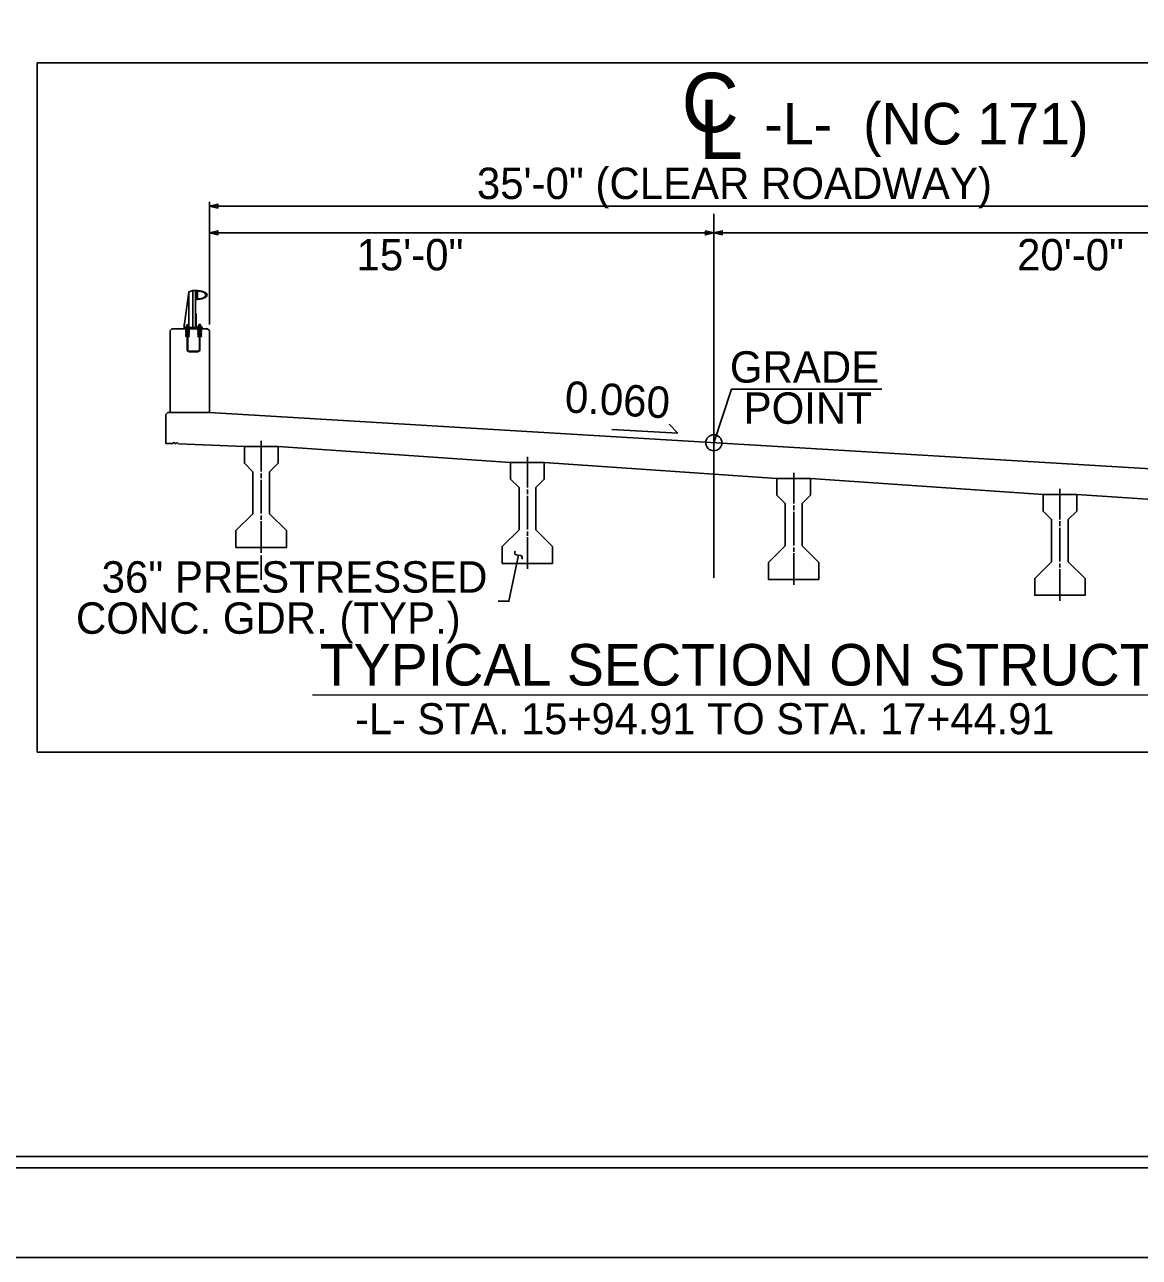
# Model space of a CAD drawing. Extents: x 2532463 to 2534146, y 189689 to 190784.
# Drawn here: x 2532655.1 to 2532903.7, y 189689.2 to 189964.1 of the extents above; entities that cross this region are included whole.
import ezdxf

# ---------------------------------------------------------------- set-up
doc = ezdxf.new("R2010")
doc.units = 0
for name, color, linetype in [('Default', 7, 'Continuous'), ('Old_Level_1', 7, 'Continuous'), ('Old_Level_18', 7, 'Continuous'), ('Old_Level_2', 7, 'Continuous'), ('Old_Level_3', 7, 'Continuous'), ('Old_Level_50', 7, 'Continuous'), ('Old_Level_51', 7, 'Continuous')]:
    doc.layers.add(name, color=color, linetype=linetype)

msp = doc.modelspace()

# ---------------------------------------------------------------- linework, layer by layer
at = {"layer": 'Default'}
for p, q in [((2532696.33, 189897.82), (2532696.33, 189924.57)), ((2532696.33, 189923.63), (2532958.83, 189923.63)), ((2532808.83, 189840.77), (2532808.83, 189921.89)), ((2532696.33, 189897.82), (2532696.33, 189918.63)), ((2532696.33, 189897.26), (2532696.33, 189918.63)), ((2532808.83, 189915.84), (2532808.83, 189918.63)), ((2532696.33, 189917.69), (2532808.83, 189917.69)), ((2532808.83, 189917.69), (2532958.83, 189917.69)), ((2532691.74, 189904.56), (2532690.71, 189896.89)), ((2532691.74, 189904.27), (2532691.7, 189904.27)), ((2532691.74, 189904.56), (2532692.63, 189904.85)), ((2532691.74, 189896.6), (2532691.74, 189904.56)), ((2532693.21, 189904.85), (2532692.63, 189904.85)), ((2532692.63, 189896.6), (2532692.63, 189904.85)), ((2532693.21, 189896.6), (2532693.21, 189904.85)), ((2532693.71, 189904.61), (2532693.71, 189903.81)), ((2532693.71, 189903.01), (2532693.71, 189903.81)), ((2532687.59, 189895.92), (2532687.98, 189896.31)), ((2532687.59, 189895.92), (2532687.59, 189877.61)), ((2532695.95, 189896.31), (2532687.98, 189896.31)), ((2532690.71, 189896.6), (2532690.71, 189896.89)), ((2532690.74, 189897.06), (2532690.74, 189897.32)), ((2532691.83, 189896.02), (2532691.05, 189896.02)), ((2532691.83, 189895.94), (2532691.05, 189895.94)), ((2532691.37, 189895.85), (2532691.22, 189895.85)), ((2532691.27, 189895.95), (2532691.27, 189896.6)), ((2532691.62, 189897.19), (2532691.28, 189897.19)), ((2532691.28, 189897.19), (2532691.28, 189896.92)), ((2532691.5, 189895.85), (2532691.37, 189895.85)), ((2532691.37, 189895.85), (2532691.37, 189891.7)), ((2532691.66, 189895.85), (2532691.5, 189895.85)), ((2532691.5, 189895.85), (2532691.5, 189891.7)), ((2532691.61, 189895.95), (2532691.61, 189896.6)), ((2532691.62, 189896.92), (2532691.62, 189897.19)), ((2532694.55, 189896.02), (2532693.77, 189896.02)), ((2532694.55, 189895.94), (2532693.77, 189895.94)), ((2532694.1, 189895.85), (2532693.94, 189895.85)), ((2532693.99, 189896.02), (2532693.99, 189896.67)), ((2532694.34, 189897.27), (2532694.01, 189897.27)), ((2532694.01, 189897.27), (2532694.01, 189896.99)), ((2532694.23, 189895.85), (2532694.1, 189895.85)), ((2532694.1, 189895.85), (2532694.1, 189891.7)), ((2532694.38, 189895.85), (2532694.23, 189895.85)), ((2532694.23, 189895.85), (2532694.23, 189891.7)), ((2532694.34, 189896.99), (2532694.34, 189897.27)), ((2532694.36, 189896.02), (2532694.36, 189896.67)), ((2532695.95, 189896.31), (2532696.33, 189895.92)), ((2532696.33, 189895.92), (2532696.33, 189877.61)), ((2532691.37, 189895.68), (2532691.05, 189895.68)), ((2532691.37, 189895.59), (2532691.05, 189895.59)), ((2532691.37, 189895.33), (2532691.05, 189895.33)), ((2532691.37, 189895.24), (2532691.05, 189895.24)), ((2532691.37, 189894.98), (2532691.05, 189894.98)), ((2532691.37, 189894.9), (2532691.05, 189894.9)), ((2532691.37, 189894.63), (2532691.05, 189894.63)), ((2532691.37, 189894.55), (2532691.05, 189894.55)), ((2532691.37, 189895.76), (2532691.22, 189895.76)), ((2532691.37, 189895.5), (2532691.22, 189895.5)), ((2532691.37, 189895.41), (2532691.22, 189895.41)), ((2532691.37, 189895.15), (2532691.22, 189895.15)), ((2532691.37, 189895.07), (2532691.22, 189895.07)), ((2532691.37, 189894.81), (2532691.22, 189894.81)), ((2532691.37, 189894.72), (2532691.22, 189894.72)), ((2532691.66, 189895.76), (2532691.5, 189895.76)), ((2532691.83, 189895.68), (2532691.5, 189895.68)), ((2532691.83, 189895.59), (2532691.5, 189895.59)), ((2532691.66, 189895.5), (2532691.5, 189895.5)), ((2532691.66, 189895.41), (2532691.5, 189895.41)), ((2532691.83, 189895.33), (2532691.5, 189895.33)), ((2532691.83, 189895.24), (2532691.5, 189895.24)), ((2532691.66, 189895.15), (2532691.5, 189895.15)), ((2532691.66, 189895.07), (2532691.5, 189895.07)), ((2532691.83, 189894.98), (2532691.5, 189894.98)), ((2532691.83, 189894.9), (2532691.5, 189894.9)), ((2532691.66, 189894.81), (2532691.5, 189894.81)), ((2532691.66, 189894.72), (2532691.5, 189894.72)), ((2532691.83, 189894.63), (2532691.5, 189894.63)), ((2532691.83, 189894.55), (2532691.5, 189894.55)), ((2532694.1, 189895.68), (2532693.77, 189895.68)), ((2532694.1, 189895.59), (2532693.77, 189895.59)), ((2532694.1, 189895.33), (2532693.77, 189895.33)), ((2532694.1, 189895.24), (2532693.77, 189895.24)), ((2532694.1, 189894.98), (2532693.77, 189894.98)), ((2532694.1, 189894.9), (2532693.77, 189894.9)), ((2532694.1, 189894.63), (2532693.77, 189894.63)), ((2532694.1, 189894.55), (2532693.77, 189894.55)), ((2532694.1, 189895.76), (2532693.94, 189895.76)), ((2532694.1, 189895.5), (2532693.94, 189895.5)), ((2532694.1, 189895.41), (2532693.94, 189895.41)), ((2532694.1, 189895.15), (2532693.94, 189895.15)), ((2532694.1, 189895.07), (2532693.94, 189895.07)), ((2532694.1, 189894.81), (2532693.94, 189894.81)), ((2532694.1, 189894.72), (2532693.94, 189894.72)), ((2532694.38, 189895.76), (2532694.23, 189895.76)), ((2532694.55, 189895.68), (2532694.23, 189895.68)), ((2532694.55, 189895.59), (2532694.23, 189895.59)), ((2532694.38, 189895.5), (2532694.23, 189895.5)), ((2532694.38, 189895.41), (2532694.23, 189895.41)), ((2532694.55, 189895.33), (2532694.23, 189895.33)), ((2532694.55, 189895.24), (2532694.23, 189895.24)), ((2532694.38, 189895.15), (2532694.23, 189895.15)), ((2532694.38, 189895.07), (2532694.23, 189895.07)), ((2532694.55, 189894.98), (2532694.23, 189894.98)), ((2532694.55, 189894.9), (2532694.23, 189894.9)), ((2532694.38, 189894.81), (2532694.23, 189894.81)), ((2532694.38, 189894.72), (2532694.23, 189894.72)), ((2532694.55, 189894.63), (2532694.23, 189894.63)), ((2532694.55, 189894.55), (2532694.23, 189894.55)), ((2532693.68, 189891.29), (2532691.92, 189891.29)), ((2532693.68, 189891.16), (2532691.92, 189891.16)), ((2532808.83, 189870.86), (2532812.79, 189882.8)), ((2532812.79, 189882.8), (2532846.28, 189882.8)), ((2532686.64, 189877.19), (2532687.04, 189877.61)), ((2532687.67, 189877.61), (2532687.04, 189877.61)), ((2532696.33, 189877.61), (2532687.67, 189877.61)), ((2532800.78, 189872.97), (2532786.07, 189873.85)), ((2532800.78, 189872.97), (2532798.85, 189875.01)), ((2532707.89, 189871.29), (2532707.89, 189864.42)), ((2532767.27, 189867.72), (2532767.27, 189860.86)), ((2532707.89, 189864.03), (2532707.89, 189862.94)), ((2532826.64, 189864.16), (2532826.64, 189857.3)), ((2532707.89, 189862.6), (2532707.89, 189855.06)), ((2532767.27, 189860.47), (2532767.27, 189859.37)), ((2532886.02, 189860.6), (2532886.02, 189853.74)), ((2532767.27, 189859.04), (2532767.27, 189851.49)), ((2532707.89, 189854.63), (2532707.89, 189853.69)), ((2532826.64, 189856.9), (2532826.64, 189855.81)), ((2532826.64, 189855.48), (2532826.64, 189847.93)), ((2532707.89, 189853.39), (2532707.89, 189846.28)), ((2532886.02, 189853.34), (2532886.02, 189852.25)), ((2532886.02, 189851.92), (2532886.02, 189844.37)), ((2532767.27, 189851.07), (2532767.27, 189850.13)), ((2532767.27, 189849.83), (2532767.27, 189842.71)), ((2532764.45, 189846.43), (2532764.52, 189846.69)), ((2532826.64, 189847.51), (2532826.64, 189846.57)), ((2532707.89, 189845.71), (2532707.89, 189840.28)), ((2532765.63, 189845.75), (2532764.81, 189845.86)), ((2532766, 189844.91), (2532766.06, 189845.11)), ((2532826.64, 189846.26), (2532826.64, 189839.15)), ((2532886.02, 189843.94), (2532886.02, 189843.01)), ((2532886.02, 189842.7), (2532886.02, 189835.59))]:
    msp.add_line(p, q, dxfattribs=at)
for points in [[(2532698.2, 189923.16), (2532696.33, 189923.63), (2532698.2, 189924.1)], [(2532698.2, 189917.22), (2532696.33, 189917.69), (2532698.2, 189918.15)], [(2532806.95, 189918.15), (2532808.83, 189917.69), (2532806.95, 189917.22)], [(2532810.7, 189917.22), (2532808.83, 189917.69), (2532810.7, 189918.15)]]:
    msp.add_lwpolyline(points, close=True, dxfattribs=at)
for points in [[(2532693.21, 189902.79), (2532693.21, 189903.17), (2532693.37, 189903.17), (2532693.37, 189903.1), (2532693.36, 189903.1), (2532693.36, 189902.94), (2532693.61, 189902.94), (2532693.64, 189903.19), (2532693.64, 189903.81), (2532693.64, 189904.42), (2532693.61, 189904.67), (2532693.36, 189904.67), (2532693.36, 189904.51), (2532693.37, 189904.51), (2532693.37, 189904.44), (2532693.21, 189904.44), (2532693.21, 189904.83)], [(2532694.72, 189896.31), (2532694.72, 189896.67), (2532693.36, 189896.67), (2532693.36, 189899.69), (2532693.21, 189899.69), (2532693.21, 189896.6), (2532690.78, 189896.6), (2532690.78, 189896.82), (2532690.71, 189896.82), (2532690.71, 189896.31), (2532691.88, 189896.31), (2532691.88, 189896.51), (2532693.07, 189896.51), (2532693.07, 189896.31), (2532694.72, 189896.31)], [(2532691.05, 189896.02), (2532691.05, 189895.94), (2532691.22, 189895.85), (2532691.22, 189895.76), (2532691.05, 189895.68), (2532691.05, 189895.59), (2532691.22, 189895.5), (2532691.22, 189895.41), (2532691.05, 189895.33), (2532691.05, 189895.24), (2532691.22, 189895.15), (2532691.22, 189895.07), (2532691.05, 189894.98), (2532691.05, 189894.9), (2532691.22, 189894.81), (2532691.22, 189894.72), (2532691.05, 189894.63), (2532691.05, 189894.55)], [(2532691.78, 189896.6), (2532691.78, 189896.66), (2532691.45, 189896.66), (2532691.11, 189896.66), (2532691.11, 189896.6)], [(2532691.7, 189896.66), (2532691.7, 189896.88), (2532691.65, 189896.92), (2532691.24, 189896.92), (2532691.2, 189896.88), (2532691.2, 189896.66), (2532691.7, 189896.66), (2532691.53, 189896.66), (2532691.53, 189896.88), (2532691.57, 189896.92), (2532691.53, 189896.88), (2532691.49, 189896.92), (2532691.41, 189896.92), (2532691.36, 189896.88), (2532691.36, 189896.66), (2532691.36, 189896.88), (2532691.32, 189896.92)], [(2532691.83, 189896.02), (2532691.83, 189895.94), (2532691.66, 189895.85), (2532691.66, 189895.76), (2532691.83, 189895.68), (2532691.83, 189895.59), (2532691.66, 189895.5), (2532691.66, 189895.41), (2532691.83, 189895.33), (2532691.83, 189895.24), (2532691.66, 189895.15), (2532691.66, 189895.07), (2532691.83, 189894.98), (2532691.83, 189894.9), (2532691.66, 189894.81), (2532691.66, 189894.72), (2532691.83, 189894.63), (2532691.83, 189894.55)], [(2532693.77, 189896.02), (2532693.77, 189895.94), (2532693.94, 189895.85), (2532693.94, 189895.76), (2532693.77, 189895.68), (2532693.77, 189895.59), (2532693.94, 189895.5), (2532693.94, 189895.41), (2532693.77, 189895.33), (2532693.77, 189895.24), (2532693.94, 189895.15), (2532693.94, 189895.07), (2532693.77, 189894.98), (2532693.77, 189894.9), (2532693.94, 189894.81), (2532693.94, 189894.72), (2532693.77, 189894.63), (2532693.77, 189894.55)], [(2532694.52, 189896.67), (2532694.52, 189896.74), (2532694.18, 189896.74), (2532693.84, 189896.74), (2532693.84, 189896.67)], [(2532694.42, 189896.74), (2532694.42, 189896.95), (2532694.38, 189896.99), (2532693.97, 189896.99), (2532693.92, 189896.95), (2532693.92, 189896.74), (2532694.42, 189896.74), (2532694.25, 189896.74), (2532694.25, 189896.95), (2532694.3, 189896.99), (2532694.25, 189896.95), (2532694.22, 189896.99), (2532694.13, 189896.99), (2532694.09, 189896.95), (2532694.09, 189896.74), (2532694.09, 189896.95), (2532694.05, 189896.99)], [(2532694.55, 189896.02), (2532694.55, 189895.94), (2532694.38, 189895.85), (2532694.38, 189895.76), (2532694.55, 189895.68), (2532694.55, 189895.59), (2532694.38, 189895.5), (2532694.38, 189895.41), (2532694.55, 189895.33), (2532694.55, 189895.24), (2532694.38, 189895.15), (2532694.38, 189895.07), (2532694.55, 189894.98), (2532694.55, 189894.9), (2532694.38, 189894.81), (2532694.38, 189894.72), (2532694.55, 189894.63), (2532694.55, 189894.55)], [(2532707.89, 189870.04), (2532711.64, 189870.04), (2532711.64, 189866.29), (2532709.77, 189864.41), (2532709.77, 189855.03), (2532713.52, 189851.28), (2532713.52, 189847.53), (2532707.89, 189847.53), (2532702.26, 189847.53), (2532702.26, 189851.28), (2532706.02, 189855.03), (2532706.02, 189864.41), (2532704.14, 189866.29), (2532704.14, 189870.04), (2532707.89, 189870.04)], [(2532767.27, 189866.47), (2532771.02, 189866.47), (2532771.02, 189862.72), (2532769.14, 189860.85), (2532769.14, 189851.47), (2532772.89, 189847.72), (2532772.89, 189843.96), (2532767.27, 189843.96), (2532761.64, 189843.96), (2532761.64, 189847.72), (2532765.39, 189851.47), (2532765.39, 189860.85), (2532763.52, 189862.72), (2532763.52, 189866.47), (2532767.27, 189866.47)], [(2532826.64, 189862.91), (2532830.39, 189862.91), (2532830.39, 189859.16), (2532828.52, 189857.28), (2532828.52, 189847.91), (2532832.27, 189844.15), (2532832.27, 189840.4), (2532826.64, 189840.4), (2532821.01, 189840.4), (2532821.01, 189844.15), (2532824.77, 189847.91), (2532824.77, 189857.28), (2532822.89, 189859.16), (2532822.89, 189862.91), (2532826.64, 189862.91)], [(2532886.02, 189859.35), (2532889.77, 189859.35), (2532889.77, 189855.6), (2532887.89, 189853.72), (2532887.89, 189844.34), (2532891.64, 189840.59), (2532891.64, 189836.84), (2532886.02, 189836.84), (2532880.39, 189836.84), (2532880.39, 189840.59), (2532884.14, 189844.34), (2532884.14, 189853.72), (2532882.27, 189855.6), (2532882.27, 189859.35), (2532886.02, 189859.35)], [(2532765.28, 189845.81), (2532763.15, 189835.53), (2532760.71, 189835.52)]]:
    msp.add_lwpolyline(points, dxfattribs=at)
for centre, radius in [((2532691.12, 189894.76), 0.0652), ((2532694.49, 189894.76), 0.0652), ((2532808.83, 189870.86), 1.79)]:
    msp.add_circle(centre, radius, dxfattribs=at)
for centre, radius, start, end in [((2532693.77, 189904.61), 0.0612, 90, 180), ((2532693.77, 189903.01), 0.0612, 180, 270), ((2532691.92, 189891.7), 0.547, 180, 270), ((2532691.92, 189891.7), 0.417, 180, 270), ((2532693.68, 189891.7), 0.417, 270, 0), ((2532693.68, 189891.7), 0.547, 270, 0), ((2532764.84, 189846.27), 0.414, 157.857, 266.1426), ((2532765.62, 189845.28), 0.466, 338.7886, 88.5875)]:
    msp.add_arc(centre, radius, start, end, dxfattribs=at)
for centre, major_axis, ratio, start_param, end_param in [((2532693.21, 189903.81), (2.61, 0), 0.39036, 6.282787, 7.853967), ((2532693.77, 189903.81), (1.74, 0), 0.495501, 6.282718, 7.853881), ((2532693.21, 189903.81), (2.61, 0), 0.39036, 4.712404, 6.282787), ((2532693.77, 189903.81), (1.74, 0), 0.495501, 4.712489, 6.282718)]:
    msp.add_ellipse(centre, major_axis=major_axis, ratio=ratio, start_param=start_param, end_param=end_param, dxfattribs=at)
at = {"layer": 'Old_Level_1'}
for p, q in [((2532958.83, 189861.86), (2532696.33, 189877.61)), ((2532711.64, 189870.04), (2532763.52, 189866.47)), ((2532771.02, 189866.47), (2532822.89, 189862.91)), ((2532830.39, 189862.91), (2532882.27, 189859.35)), ((2532889.77, 189859.35), (2532941.64, 189855.79)), ((2532719.37, 189814.66), (2532932.88, 189814.58))]:
    msp.add_line(p, q, dxfattribs=at)
msp.add_lwpolyline([(2532704.14, 189870.04), (2532689.47, 189870.62), (2532689.15, 189870.89), (2532688.83, 189870.64), (2532688.51, 189870.9), (2532688.19, 189870.67), (2532686.64, 189870.73), (2532686.64, 189877.19)], dxfattribs=at)
at = {"layer": 'Old_Level_18'}
msp.add_lwpolyline([(2534129.31, 190761.68), (2532629.31, 190761.68), (2532629.31, 189711.68), (2534129.31, 189711.68)], close=True, dxfattribs=at)
at = {"layer": 'Old_Level_2'}
msp.add_lwpolyline([(2532657.96, 189955.63), (2532992.3, 189955.63), (2532992.3, 189801.87), (2532657.96, 189801.87)], close=True, dxfattribs=at)
at = {"layer": 'Old_Level_50'}
msp.add_lwpolyline([(2532475.81, 189709.18), (2534141.81, 189709.18), (2534141.81, 190764.18), (2532475.81, 190764.18)], close=True, dxfattribs=at)
at = {"layer": 'Old_Level_51'}
msp.add_lwpolyline([(2532462.81, 189689.18), (2534146.31, 189689.18), (2534146.31, 190784.18), (2532462.81, 190784.18)], close=True, dxfattribs=at)

# ---------------------------------------------------------------- texts
at = {"layer": 'Default'}
for s, p in [('35\'-0" (CLEAR ROADWAY)', (2532755.99, 189925.22)), ('15\'-0"', (2532729.15, 189909.31)), ('20\'-0"', (2532876.46, 189909.31)), ('GRADE', (2532812.42, 189884.27)), ('POINT', (2532815.48, 189875.1)), ('36" PRESTRESSED', (2532672.31, 189837.44)), ('CONC. GDR. (TYP.)', (2532666.58, 189828.26))]:
    msp.add_text(s, height=7, dxfattribs=at).set_placement(p)
msp.add_text('0.060', height=7, rotation=356.5664, dxfattribs=at).set_placement((2532775.45, 189877.67))
at = {"layer": 'Old_Level_3'}
for s, height, rotation, p in [('C', 13.24, 359.9998, (2532801.62, 189940.13)), ('L', 13.24, 359.9998, (2532805.47, 189934.14)), ('-L-  (NC 171)', 9.2713, 359.9998, (2532820.08, 189937.39)), ('TYPICAL SECTION ON STRUCTURE', 9.2713, 0.0002, (2532720.93, 189816.71)), ('-L- STA. 15+94.91 TO STA. 17+44.91', 6.9255, 0.0002, (2532728.81, 189805.85))]:
    msp.add_text(s, height=height, rotation=rotation, dxfattribs=at).set_placement(p)

doc.saveas('drawing.dxf')
